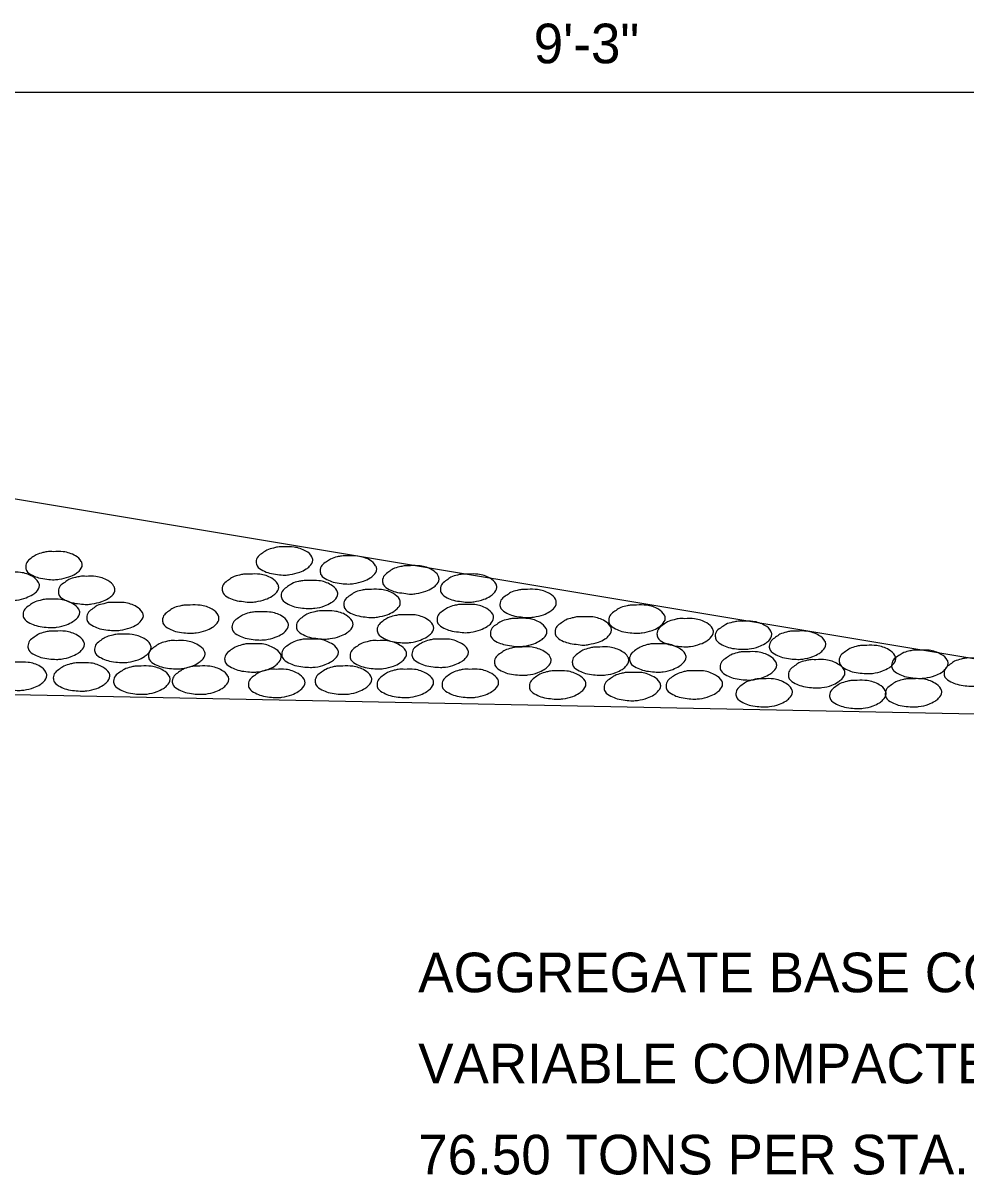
# Model space of a CAD drawing. Extents: x -2842 to 2681, y -2139 to 474.
# Drawn here: x 44.4 to 187.2, y -1103.6 to -929.2 of the extents above; entities that cross this region are included whole.
import ezdxf

# ---------------------------------------------------------------- set-up
doc = ezdxf.new("R2010")
doc.units = 0
doc.layers.add('Default', color=7, linetype='Continuous')

msp = doc.modelspace()

# ---------------------------------------------------------------- linework, layer by layer
at = {"layer": 'Default'}
for p, q in [((20.9, -939.7), (245.22, -939.7)), ((20.9, -997.55), (412.13, -1062.76)), ((-136.65, -1027.3), (245.22, -1034.95))]:
    msp.add_line(p, q, dxfattribs=at)
for points in [[(49, -1009.27), (50.51, -1009.28), (52.35, -1009.89), (53.24, -1010.76), (53.38, -1011.25), (52.89, -1012.21), (52.36, -1012.62), (51.37, -1013.07), (49.89, -1013.44), (49.15, -1013.51), (48.02, -1013.43), (46.78, -1013.22), (45.85, -1012.84), (44.93, -1012.12), (44.82, -1011.54), (45.09, -1010.73), (45.76, -1010.17), (46.41, -1009.73), (47.41, -1009.41), (48.05, -1009.28), (49, -1009.27)], [(83.92, -1008.55), (85.45, -1008.57), (87.24, -1009.19), (88.16, -1010.05), (88.27, -1010.56), (87.78, -1011.48), (87.28, -1011.88), (86.3, -1012.37), (84.81, -1012.74), (84.06, -1012.82), (82.94, -1012.71), (81.71, -1012.51), (80.74, -1012.12), (79.85, -1011.42), (79.71, -1010.82), (79.99, -1010), (80.68, -1009.47), (81.33, -1009.05), (82.33, -1008.71), (82.95, -1008.57), (83.92, -1008.55)], [(93.6, -1009.89), (95.09, -1009.94), (96.91, -1010.54), (97.8, -1011.39), (97.96, -1011.88), (97.46, -1012.84), (96.95, -1013.24), (95.95, -1013.72), (94.48, -1014.1), (93.74, -1014.16), (92.61, -1014.08), (91.37, -1013.86), (90.43, -1013.47), (89.53, -1012.79), (89.4, -1012.16), (89.65, -1011.35), (90.34, -1010.79), (90.98, -1010.39), (91.98, -1010.05), (92.63, -1009.94), (93.6, -1009.89)], [(103.05, -1011.39), (104.55, -1011.42), (106.39, -1012.04), (107.25, -1012.9), (107.39, -1013.41), (106.92, -1014.35), (106.4, -1014.75), (105.41, -1015.25), (103.94, -1015.59), (103.18, -1015.69), (102.07, -1015.56), (100.81, -1015.36), (99.86, -1014.97), (98.97, -1014.28), (98.83, -1013.68), (99.13, -1012.85), (99.81, -1012.31), (100.44, -1011.87), (101.43, -1011.57), (102.09, -1011.42), (103.05, -1011.39)], [(42.56, -1012.4), (44.04, -1012.41), (45.88, -1013.04), (46.75, -1013.91), (46.91, -1014.41), (46.44, -1015.34), (45.9, -1015.75), (44.91, -1016.23), (43.45, -1016.61), (42.67, -1016.65), (41.58, -1016.59), (40.33, -1016.39), (39.38, -1015.98), (38.49, -1015.28), (38.35, -1014.69), (38.63, -1013.86), (39.32, -1013.3), (39.93, -1012.87), (40.96, -1012.57), (41.6, -1012.41), (42.56, -1012.4)], [(53.97, -1013.01), (55.46, -1013.02), (57.27, -1013.65), (58.18, -1014.52), (58.33, -1015), (57.85, -1015.94), (57.3, -1016.37), (56.32, -1016.82), (54.84, -1017.18), (54.09, -1017.26), (53, -1017.17), (51.74, -1016.96), (50.8, -1016.59), (49.89, -1015.89), (49.76, -1015.28), (50.04, -1014.46), (50.73, -1013.91), (51.35, -1013.47), (52.36, -1013.18), (53.02, -1013.02), (53.97, -1013.01)], [(78.75, -1012.66), (80.27, -1012.68), (82.08, -1013.29), (82.98, -1014.16), (83.12, -1014.67), (82.64, -1015.59), (82.11, -1016), (81.14, -1016.48), (79.65, -1016.84), (78.9, -1016.93), (77.78, -1016.82), (76.55, -1016.62), (75.58, -1016.23), (74.71, -1015.53), (74.55, -1014.94), (74.83, -1014.11), (75.52, -1013.58), (76.16, -1013.13), (77.19, -1012.82), (77.79, -1012.68), (78.75, -1012.66)], [(111.78, -1012.66), (113.29, -1012.68), (115.13, -1013.29), (116.02, -1014.16), (116.14, -1014.67), (115.66, -1015.59), (115.15, -1016), (114.17, -1016.48), (112.68, -1016.84), (111.92, -1016.93), (110.81, -1016.82), (109.6, -1016.62), (108.6, -1016.23), (107.75, -1015.53), (107.6, -1014.94), (107.89, -1014.11), (108.56, -1013.58), (109.19, -1013.13), (110.19, -1012.82), (110.83, -1012.68), (111.78, -1012.66)], [(87.72, -1013.65), (89.22, -1013.66), (91.02, -1014.28), (91.93, -1015.13), (92.08, -1015.66), (91.59, -1016.59), (91.06, -1016.98), (90.07, -1017.48), (88.59, -1017.82), (87.83, -1017.88), (86.71, -1017.81), (85.49, -1017.6), (84.54, -1017.21), (83.64, -1016.5), (83.48, -1015.92), (83.78, -1015.09), (84.46, -1014.55), (85.1, -1014.11), (86.12, -1013.77), (86.75, -1013.66), (87.72, -1013.65)], [(97.16, -1014.97), (98.68, -1015), (100.51, -1015.61), (101.4, -1016.48), (101.53, -1016.98), (101.04, -1017.93), (100.53, -1018.32), (99.55, -1018.82), (98.07, -1019.16), (97.32, -1019.24), (96.2, -1019.15), (94.97, -1018.93), (94, -1018.55), (93.11, -1017.85), (92.99, -1017.26), (93.24, -1016.43), (93.94, -1015.9), (94.58, -1015.47), (95.57, -1015.13), (96.23, -1015), (97.16, -1014.97)], [(120.8, -1014.97), (122.3, -1015), (124.12, -1015.61), (125.04, -1016.48), (125.15, -1016.98), (124.7, -1017.93), (124.17, -1018.32), (123.19, -1018.82), (121.71, -1019.16), (120.94, -1019.24), (119.81, -1019.15), (118.58, -1018.93), (117.64, -1018.55), (116.77, -1017.85), (116.61, -1017.26), (116.88, -1016.43), (117.58, -1015.9), (118.2, -1015.47), (119.23, -1015.13), (119.87, -1015), (120.8, -1014.97)], [(48.61, -1016.48), (50.12, -1016.5), (51.94, -1017.14), (52.86, -1017.99), (53, -1018.49), (52.5, -1019.43), (51.97, -1019.85), (51.01, -1020.33), (49.5, -1020.7), (48.76, -1020.75), (47.63, -1020.67), (46.41, -1020.46), (45.46, -1020.07), (44.57, -1019.36), (44.43, -1018.74), (44.7, -1017.96), (45.38, -1017.4), (46.04, -1016.96), (47.02, -1016.64), (47.64, -1016.5), (48.61, -1016.48)], [(58.27, -1016.96), (59.75, -1016.98), (61.59, -1017.6), (62.48, -1018.48), (62.63, -1018.99), (62.13, -1019.89), (61.6, -1020.33), (60.62, -1020.78), (59.13, -1021.17), (58.38, -1021.22), (57.26, -1021.14), (56.04, -1020.94), (55.09, -1020.55), (54.19, -1019.85), (54.05, -1019.24), (54.33, -1018.44), (55, -1017.87), (55.65, -1017.43), (56.66, -1017.14), (57.27, -1016.98), (58.27, -1016.96)], [(69.72, -1017.35), (71.23, -1017.37), (73.07, -1017.99), (73.95, -1018.87), (74.07, -1019.36), (73.62, -1020.28), (73.09, -1020.72), (72.09, -1021.19), (70.61, -1021.55), (69.88, -1021.62), (68.74, -1021.53), (67.49, -1021.33), (66.57, -1020.94), (65.66, -1020.24), (65.53, -1019.64), (65.81, -1018.82), (66.48, -1018.27), (67.12, -1017.82), (68.13, -1017.51), (68.77, -1017.37), (69.72, -1017.35)], [(80.24, -1018.38), (81.75, -1018.4), (83.59, -1019.02), (84.46, -1019.88), (84.6, -1020.38), (84.12, -1021.33), (83.61, -1021.73), (82.61, -1022.22), (81.14, -1022.59), (80.38, -1022.64), (79.27, -1022.56), (78.03, -1022.34), (77.06, -1021.95), (76.17, -1021.25), (76.05, -1020.67), (76.33, -1019.85), (77.02, -1019.3), (77.64, -1018.87), (78.65, -1018.52), (79.29, -1018.4), (80.24, -1018.38)], [(90.03, -1018.24), (91.51, -1018.27), (93.35, -1018.88), (94.22, -1019.75), (94.37, -1020.25), (93.88, -1021.19), (93.36, -1021.59), (92.36, -1022.08), (90.92, -1022.43), (90.12, -1022.51), (89.05, -1022.42), (87.78, -1022.22), (86.83, -1021.83), (85.94, -1021.13), (85.8, -1020.53), (86.1, -1019.69), (86.79, -1019.15), (87.39, -1018.71), (88.41, -1018.4), (89.06, -1018.27), (90.03, -1018.24)], [(111.3, -1017.26), (112.81, -1017.28), (114.62, -1017.88), (115.52, -1018.74), (115.65, -1019.26), (115.16, -1020.22), (114.66, -1020.6), (113.68, -1021.09), (112.2, -1021.47), (111.44, -1021.53), (110.33, -1021.42), (109.09, -1021.22), (108.12, -1020.83), (107.23, -1020.14), (107.09, -1019.54), (107.37, -1018.71), (108.07, -1018.18), (108.7, -1017.76), (109.69, -1017.42), (110.35, -1017.28), (111.3, -1017.26)], [(137.29, -1017.35), (138.8, -1017.37), (140.63, -1017.99), (141.51, -1018.87), (141.65, -1019.36), (141.16, -1020.28), (140.64, -1020.72), (139.64, -1021.19), (138.16, -1021.55), (137.42, -1021.62), (136.31, -1021.53), (135.06, -1021.33), (134.11, -1020.94), (133.22, -1020.24), (133.08, -1019.64), (133.36, -1018.82), (134.03, -1018.27), (134.69, -1017.82), (135.69, -1017.51), (136.34, -1017.37), (137.29, -1017.35)], [(102.24, -1018.82), (103.76, -1018.85), (105.56, -1019.46), (106.45, -1020.33), (106.59, -1020.8), (106.09, -1021.75), (105.58, -1022.15), (104.61, -1022.64), (103.12, -1023.01), (102.37, -1023.07), (101.26, -1023), (100.03, -1022.79), (99.07, -1022.4), (98.18, -1021.7), (98.02, -1021.09), (98.32, -1020.27), (99, -1019.71), (99.64, -1019.3), (100.62, -1018.99), (101.28, -1018.85), (102.24, -1018.82)], [(119.37, -1019.36), (120.9, -1019.4), (122.69, -1020), (123.59, -1020.89), (123.73, -1021.37), (123.25, -1022.31), (122.7, -1022.73), (121.75, -1023.2), (120.24, -1023.57), (119.51, -1023.63), (118.39, -1023.54), (117.17, -1023.31), (116.21, -1022.96), (115.32, -1022.25), (115.16, -1021.64), (115.44, -1020.8), (116.13, -1020.27), (116.78, -1019.85), (117.8, -1019.52), (118.4, -1019.4), (119.37, -1019.36)], [(129.14, -1019.13), (130.68, -1019.15), (132.49, -1019.77), (133.38, -1020.63), (133.49, -1021.14), (133.02, -1022.08), (132.51, -1022.48), (131.54, -1022.98), (130.04, -1023.31), (129.3, -1023.42), (128.17, -1023.29), (126.96, -1023.09), (125.99, -1022.73), (125.1, -1022), (124.95, -1021.41), (125.23, -1020.58), (125.91, -1020.05), (126.57, -1019.61), (127.55, -1019.3), (128.19, -1019.15), (129.14, -1019.13)], [(144.58, -1019.41), (146.09, -1019.43), (147.92, -1020.05), (148.81, -1020.92), (148.93, -1021.41), (148.45, -1022.34), (147.93, -1022.78), (146.95, -1023.24), (145.47, -1023.62), (144.72, -1023.67), (143.6, -1023.59), (142.37, -1023.37), (141.39, -1023), (140.52, -1022.29), (140.39, -1021.7), (140.66, -1020.89), (141.34, -1020.33), (142, -1019.88), (142.98, -1019.57), (143.62, -1019.43), (144.58, -1019.41)], [(153.4, -1019.82), (154.91, -1019.83), (156.74, -1020.44), (157.63, -1021.3), (157.77, -1021.8), (157.3, -1022.76), (156.75, -1023.17), (155.79, -1023.63), (154.32, -1023.99), (153.54, -1024.05), (152.44, -1023.98), (151.19, -1023.77), (150.24, -1023.37), (149.37, -1022.65), (149.21, -1022.08), (149.46, -1021.25), (150.18, -1020.72), (150.8, -1020.27), (151.83, -1019.96), (152.47, -1019.83), (153.4, -1019.82)], [(49.32, -1021.3), (50.84, -1021.31), (52.66, -1021.95), (53.58, -1022.81), (53.72, -1023.31), (53.22, -1024.24), (52.69, -1024.66), (51.72, -1025.15), (50.21, -1025.52), (49.48, -1025.57), (48.34, -1025.49), (47.13, -1025.27), (46.18, -1024.88), (45.29, -1024.18), (45.15, -1023.56), (45.41, -1022.78), (46.1, -1022.22), (46.75, -1021.78), (47.73, -1021.45), (48.36, -1021.31), (49.32, -1021.3)], [(59.42, -1021.78), (60.93, -1021.8), (62.76, -1022.43), (63.68, -1023.29), (63.82, -1023.79), (63.32, -1024.72), (62.79, -1025.15), (61.82, -1025.63), (60.31, -1026), (59.58, -1026.05), (58.44, -1025.97), (57.23, -1025.75), (56.27, -1025.36), (55.39, -1024.66), (55.25, -1024.04), (55.51, -1023.26), (56.2, -1022.7), (56.85, -1022.26), (57.83, -1021.94), (58.46, -1021.8), (59.42, -1021.78)], [(161.57, -1021.3), (163.08, -1021.31), (164.9, -1021.95), (165.82, -1022.81), (165.96, -1023.31), (165.46, -1024.24), (164.93, -1024.66), (163.97, -1025.15), (162.46, -1025.52), (161.72, -1025.57), (160.59, -1025.49), (159.37, -1025.27), (158.42, -1024.88), (157.53, -1024.18), (157.39, -1023.56), (157.66, -1022.78), (158.34, -1022.22), (159, -1021.78), (159.98, -1021.45), (160.6, -1021.31), (161.57, -1021.3)], [(67.59, -1022.75), (69.1, -1022.76), (70.92, -1023.4), (71.84, -1024.26), (71.98, -1024.76), (71.48, -1025.69), (70.95, -1026.11), (69.99, -1026.59), (68.48, -1026.97), (67.74, -1027.02), (66.61, -1026.94), (65.39, -1026.72), (64.44, -1026.33), (63.55, -1025.63), (63.41, -1025.01), (63.68, -1024.23), (64.36, -1023.67), (65.02, -1023.23), (66, -1022.9), (66.62, -1022.76), (67.59, -1022.75)], [(79.12, -1023.23), (80.63, -1023.24), (82.45, -1023.88), (83.37, -1024.74), (83.51, -1025.24), (83.01, -1026.17), (82.49, -1026.59), (81.52, -1027.08), (80.01, -1027.45), (79.27, -1027.5), (78.14, -1027.42), (76.92, -1027.2), (75.97, -1026.81), (75.08, -1026.11), (74.94, -1025.49), (75.21, -1024.71), (75.89, -1024.15), (76.55, -1023.71), (77.53, -1023.38), (78.15, -1023.24), (79.12, -1023.23)], [(87.77, -1022.51), (89.28, -1022.53), (91.1, -1023.17), (92.02, -1024.02), (92.16, -1024.52), (91.66, -1025.46), (91.13, -1025.88), (90.17, -1026.36), (88.66, -1026.74), (87.92, -1026.78), (86.79, -1026.7), (85.57, -1026.49), (84.62, -1026.1), (83.73, -1025.39), (83.59, -1024.77), (83.86, -1023.99), (84.54, -1023.43), (85.2, -1023), (86.18, -1022.67), (86.8, -1022.53), (87.77, -1022.51)], [(98.1, -1022.75), (99.61, -1022.76), (101.43, -1023.4), (102.35, -1024.26), (102.49, -1024.76), (101.99, -1025.69), (101.47, -1026.11), (100.5, -1026.59), (98.99, -1026.97), (98.26, -1027.02), (97.12, -1026.94), (95.9, -1026.72), (94.95, -1026.33), (94.06, -1025.63), (93.92, -1025.01), (94.19, -1024.23), (94.87, -1023.67), (95.53, -1023.23), (96.51, -1022.9), (97.13, -1022.76), (98.1, -1022.75)], [(107.46, -1022.51), (108.98, -1022.53), (110.8, -1023.17), (111.72, -1024.02), (111.86, -1024.52), (111.36, -1025.46), (110.83, -1025.88), (109.86, -1026.36), (108.35, -1026.74), (107.62, -1026.78), (106.48, -1026.7), (105.27, -1026.49), (104.32, -1026.1), (103.43, -1025.39), (103.29, -1024.77), (103.55, -1023.99), (104.24, -1023.43), (104.89, -1023), (105.88, -1022.67), (106.5, -1022.53), (107.46, -1022.51)], [(119.96, -1023.71), (121.47, -1023.73), (123.3, -1024.37), (124.22, -1025.22), (124.36, -1025.72), (123.86, -1026.66), (123.33, -1027.08), (122.36, -1027.56), (120.85, -1027.93), (120.12, -1027.98), (118.98, -1027.9), (117.76, -1027.69), (116.81, -1027.3), (115.93, -1026.59), (115.79, -1025.97), (116.05, -1025.19), (116.74, -1024.63), (117.39, -1024.2), (118.37, -1023.87), (119, -1023.73), (119.96, -1023.71)], [(131.74, -1023.71), (133.25, -1023.73), (135.08, -1024.37), (136, -1025.22), (136.14, -1025.72), (135.64, -1026.66), (135.11, -1027.08), (134.14, -1027.56), (132.63, -1027.93), (131.9, -1027.98), (130.76, -1027.9), (129.55, -1027.69), (128.6, -1027.3), (127.71, -1026.59), (127.57, -1025.97), (127.83, -1025.19), (128.52, -1024.63), (129.17, -1024.2), (130.15, -1023.87), (130.78, -1023.73), (131.74, -1023.71)], [(140.41, -1023.23), (141.92, -1023.24), (143.74, -1023.88), (144.66, -1024.74), (144.8, -1025.24), (144.3, -1026.17), (143.77, -1026.59), (142.81, -1027.08), (141.3, -1027.45), (140.56, -1027.5), (139.43, -1027.42), (138.21, -1027.2), (137.26, -1026.81), (136.37, -1026.11), (136.23, -1025.49), (136.5, -1024.71), (137.18, -1024.15), (137.84, -1023.71), (138.82, -1023.38), (139.44, -1023.24), (140.41, -1023.23)], [(172.15, -1023.46), (173.66, -1023.48), (175.48, -1024.12), (176.4, -1024.97), (176.54, -1025.47), (176.05, -1026.41), (175.52, -1026.83), (174.55, -1027.31), (173.04, -1027.69), (172.31, -1027.73), (171.17, -1027.65), (169.95, -1027.44), (169, -1027.05), (168.11, -1026.35), (167.97, -1025.72), (168.24, -1024.94), (168.92, -1024.38), (169.58, -1023.95), (170.56, -1023.62), (171.18, -1023.48), (172.15, -1023.46)], [(154.12, -1024.43), (155.63, -1024.44), (157.45, -1025.08), (158.37, -1025.94), (158.51, -1026.44), (158.02, -1027.37), (157.49, -1027.79), (156.52, -1028.28), (155.01, -1028.65), (154.28, -1028.7), (153.14, -1028.62), (151.92, -1028.4), (150.97, -1028.01), (150.08, -1027.31), (149.94, -1026.69), (150.21, -1025.91), (150.89, -1025.35), (151.55, -1024.91), (152.53, -1024.58), (153.15, -1024.44), (154.12, -1024.43)], [(164.45, -1025.63), (165.96, -1025.64), (167.79, -1026.28), (168.71, -1027.14), (168.85, -1027.64), (168.35, -1028.57), (167.82, -1028.99), (166.85, -1029.48), (165.34, -1029.85), (164.61, -1029.9), (163.47, -1029.82), (162.25, -1029.6), (161.3, -1029.21), (160.42, -1028.51), (160.28, -1027.89), (160.54, -1027.11), (161.23, -1026.55), (161.88, -1026.11), (162.86, -1025.78), (163.49, -1025.64), (164.45, -1025.63)], [(180.08, -1024.18), (181.59, -1024.2), (183.42, -1024.83), (184.34, -1025.69), (184.48, -1026.19), (183.98, -1027.12), (183.45, -1027.55), (182.48, -1028.03), (180.97, -1028.4), (180.24, -1028.45), (179.1, -1028.37), (177.88, -1028.15), (176.93, -1027.76), (176.05, -1027.06), (175.91, -1026.44), (176.17, -1025.66), (176.86, -1025.1), (177.51, -1024.66), (178.49, -1024.34), (179.12, -1024.2), (180.08, -1024.18)], [(188.01, -1025.38), (189.52, -1025.39), (191.35, -1026.03), (192.27, -1026.89), (192.41, -1027.39), (191.91, -1028.32), (191.38, -1028.75), (190.41, -1029.23), (188.9, -1029.6), (188.17, -1029.65), (187.03, -1029.57), (185.82, -1029.35), (184.87, -1028.96), (183.98, -1028.26), (183.84, -1027.64), (184.1, -1026.86), (184.79, -1026.3), (185.44, -1025.86), (186.42, -1025.54), (187.05, -1025.39), (188.01, -1025.38)], [(43.64, -1025.99), (45.18, -1026.03), (47, -1026.64), (47.89, -1027.51), (48, -1028.01), (47.53, -1028.96), (47.02, -1029.37), (46.04, -1029.85), (44.56, -1030.21), (43.79, -1030.27), (42.69, -1030.18), (41.47, -1029.96), (40.5, -1029.59), (39.62, -1028.89), (39.46, -1028.28), (39.73, -1027.45), (40.41, -1026.92), (41.07, -1026.49), (42.06, -1026.16), (42.7, -1026.03), (43.64, -1025.99)], [(53.17, -1026.11), (54.69, -1026.13), (56.51, -1026.77), (57.43, -1027.62), (57.57, -1028.12), (57.07, -1029.06), (56.54, -1029.48), (55.57, -1029.96), (54.06, -1030.33), (53.33, -1030.38), (52.19, -1030.3), (50.98, -1030.09), (50.03, -1029.7), (49.14, -1028.99), (49, -1028.37), (49.26, -1027.59), (49.95, -1027.03), (50.6, -1026.59), (51.58, -1026.27), (52.21, -1026.13), (53.17, -1026.11)], [(62.31, -1026.59), (63.82, -1026.61), (65.64, -1027.25), (66.56, -1028.11), (66.7, -1028.61), (66.2, -1029.54), (65.67, -1029.96), (64.7, -1030.44), (63.19, -1030.82), (62.46, -1030.86), (61.32, -1030.79), (60.11, -1030.57), (59.16, -1030.18), (58.27, -1029.48), (58.13, -1028.85), (58.39, -1028.08), (59.08, -1027.51), (59.73, -1027.08), (60.72, -1026.75), (61.34, -1026.61), (62.31, -1026.59)], [(71.19, -1026.59), (72.7, -1026.61), (74.52, -1027.25), (75.44, -1028.11), (75.58, -1028.61), (75.08, -1029.54), (74.55, -1029.96), (73.59, -1030.44), (72.08, -1030.82), (71.34, -1030.86), (70.21, -1030.79), (68.99, -1030.57), (68.04, -1030.18), (67.15, -1029.48), (67.01, -1028.85), (67.28, -1028.08), (67.96, -1027.51), (68.62, -1027.08), (69.6, -1026.75), (70.22, -1026.61), (71.19, -1026.59)], [(82.72, -1027.08), (84.23, -1027.09), (86.05, -1027.73), (86.97, -1028.59), (87.11, -1029.09), (86.61, -1030.02), (86.08, -1030.44), (85.12, -1030.93), (83.61, -1031.3), (82.87, -1031.35), (81.74, -1031.27), (80.52, -1031.05), (79.57, -1030.66), (78.68, -1029.96), (78.54, -1029.34), (78.81, -1028.56), (79.49, -1028), (80.15, -1027.56), (81.13, -1027.23), (81.75, -1027.09), (82.72, -1027.08)], [(92.82, -1026.59), (94.33, -1026.61), (96.15, -1027.25), (97.07, -1028.11), (97.21, -1028.61), (96.71, -1029.54), (96.18, -1029.96), (95.22, -1030.44), (93.7, -1030.82), (92.97, -1030.86), (91.83, -1030.79), (90.62, -1030.57), (89.67, -1030.18), (88.78, -1029.48), (88.64, -1028.85), (88.91, -1028.08), (89.59, -1027.51), (90.25, -1027.08), (91.23, -1026.75), (91.85, -1026.61), (92.82, -1026.59)], [(102.18, -1027.08), (103.69, -1027.09), (105.52, -1027.73), (106.44, -1028.59), (106.58, -1029.09), (106.08, -1030.02), (105.55, -1030.44), (104.58, -1030.93), (103.07, -1031.3), (102.34, -1031.35), (101.2, -1031.27), (99.98, -1031.05), (99.03, -1030.66), (98.15, -1029.96), (98.01, -1029.34), (98.27, -1028.56), (98.96, -1028), (99.61, -1027.56), (100.59, -1027.23), (101.22, -1027.09), (102.18, -1027.08)], [(112.03, -1027.08), (113.54, -1027.09), (115.37, -1027.73), (116.28, -1028.59), (116.42, -1029.09), (115.93, -1030.02), (115.4, -1030.44), (114.43, -1030.93), (112.92, -1031.3), (112.19, -1031.35), (111.05, -1031.27), (109.83, -1031.05), (108.88, -1030.66), (107.99, -1029.96), (107.85, -1029.34), (108.12, -1028.56), (108.8, -1028), (109.46, -1027.56), (110.44, -1027.23), (111.06, -1027.09), (112.03, -1027.08)], [(125.24, -1027.33), (126.76, -1027.34), (128.58, -1027.98), (129.5, -1028.84), (129.64, -1029.34), (129.14, -1030.27), (128.61, -1030.69), (127.64, -1031.18), (126.13, -1031.55), (125.4, -1031.6), (124.26, -1031.52), (123.05, -1031.3), (122.1, -1030.91), (121.21, -1030.21), (121.07, -1029.59), (121.33, -1028.81), (122.02, -1028.25), (122.67, -1027.81), (123.66, -1027.48), (124.28, -1027.34), (125.24, -1027.33)], [(145.94, -1027.31), (147.45, -1027.33), (149.27, -1027.97), (150.19, -1028.82), (150.33, -1029.32), (149.83, -1030.26), (149.3, -1030.68), (148.34, -1031.16), (146.83, -1031.53), (146.09, -1031.58), (144.96, -1031.5), (143.74, -1031.29), (142.79, -1030.9), (141.9, -1030.19), (141.76, -1029.57), (142.03, -1028.79), (142.71, -1028.23), (143.37, -1027.79), (144.35, -1027.47), (144.97, -1027.33), (145.94, -1027.31)], [(136.56, -1027.56), (138.07, -1027.58), (139.89, -1028.22), (140.81, -1029.07), (140.95, -1029.57), (140.45, -1030.51), (139.92, -1030.93), (138.96, -1031.41), (137.45, -1031.78), (136.71, -1031.83), (135.58, -1031.75), (134.36, -1031.53), (133.41, -1031.15), (132.52, -1030.44), (132.38, -1029.82), (132.65, -1029.04), (133.33, -1028.48), (133.99, -1028.04), (134.97, -1027.72), (135.59, -1027.58), (136.56, -1027.56)], [(156.52, -1028.51), (158.03, -1028.53), (159.85, -1029.17), (160.77, -1030.02), (160.91, -1030.52), (160.42, -1031.46), (159.89, -1031.88), (158.92, -1032.36), (157.41, -1032.73), (156.68, -1032.78), (155.54, -1032.7), (154.32, -1032.49), (153.37, -1032.1), (152.48, -1031.39), (152.34, -1030.77), (152.61, -1029.99), (153.29, -1029.43), (153.95, -1028.99), (154.93, -1028.67), (155.55, -1028.53), (156.52, -1028.51)], [(170.7, -1028.76), (172.21, -1028.78), (174.04, -1029.42), (174.95, -1030.27), (175.09, -1030.77), (174.6, -1031.71), (174.07, -1032.13), (173.1, -1032.61), (171.59, -1032.98), (170.86, -1033.03), (169.72, -1032.95), (168.5, -1032.73), (167.55, -1032.34), (166.66, -1031.64), (166.52, -1031.02), (166.79, -1030.24), (167.47, -1029.68), (168.13, -1029.24), (169.11, -1028.92), (169.73, -1028.78), (170.7, -1028.76)], [(179.12, -1028.51), (180.63, -1028.53), (182.45, -1029.17), (183.37, -1030.02), (183.51, -1030.52), (183.01, -1031.46), (182.48, -1031.88), (181.52, -1032.36), (180, -1032.73), (179.27, -1032.78), (178.13, -1032.7), (176.92, -1032.49), (175.97, -1032.1), (175.08, -1031.39), (174.94, -1030.77), (175.2, -1029.99), (175.89, -1029.43), (176.54, -1028.99), (177.53, -1028.67), (178.15, -1028.53), (179.12, -1028.51)]]:
    msp.add_spline(points, degree=3, dxfattribs=at)

# ---------------------------------------------------------------- texts
for s, p in [('9\'-3"', (121.72, -935.31)), ('AGGREGATE BASE COURSE (CLASS 7)', (104.24, -1075.98)), ('VARIABLE COMPACTED DEPTH', (104.24, -1089.77)), ('76.50 TONS PER STA.', (104.24, -1103.56))]:
    msp.add_text(s, height=6, dxfattribs=at).set_placement(p)

doc.saveas('drawing.dxf')
